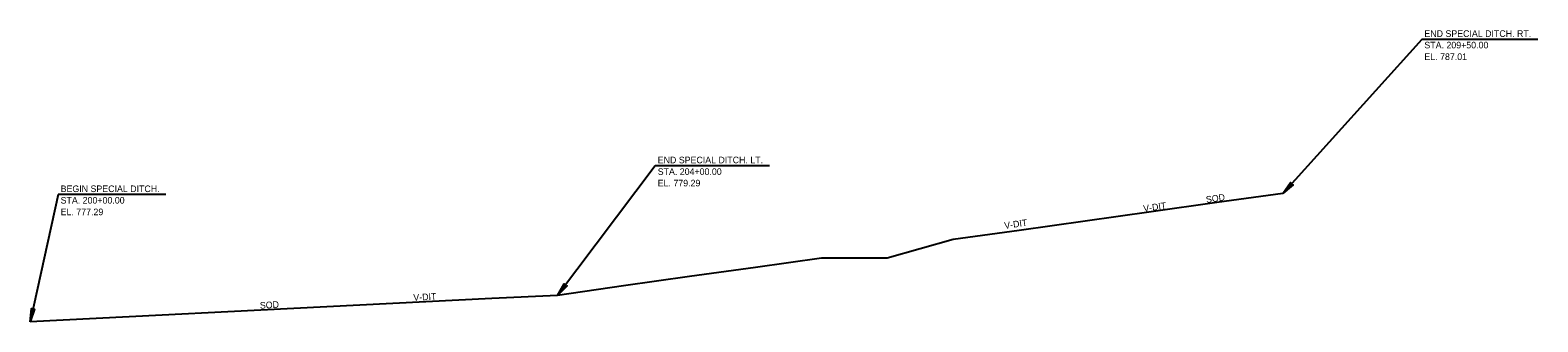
# Model space of a CAD drawing. Extents: x -50 to 1838305, y -27 to 820775.
# Drawn here: x 1837162 to 1838305, y 820554 to 820775 of the extents above; entities that cross this region are included whole.
import ezdxf

# ---------------------------------------------------------------- set-up
doc = ezdxf.new("R2010")
doc.units = 0
doc.layers.add('DESIGN - DRAINAGE - Special Ditches', color=7, linetype='Continuous')
doc.layers.add('DESIGN - PROFILE - Drainage - Bridges Drains and Ditches Text', color=7, linetype='Continuous')

msp = doc.modelspace()

# ---------------------------------------------------------------- linework, layer by layer
at = {"layer": 'DESIGN - DRAINAGE - Special Ditches'}
msp.add_lwpolyline([(1838111.6, 820651.5), (1838061.6, 820644.5), (1838011.6, 820637.5), (1837961.6, 820630.5), (1837911.6, 820623.5), (1837861.6, 820616.5), (1837811.6, 820602.5), (1837761.6, 820602.5), (1837711.6, 820595.5), (1837661.6, 820588.5), (1837611.6, 820581.5), (1837561.6, 820574.3), (1837511.6, 820571.8), (1837461.6, 820569.3), (1837411.6, 820566.8), (1837361.6, 820564.3), (1837311.6, 820561.8), (1837261.6, 820559.3), (1837211.6, 820556.8), (1837161.6, 820554.3)], dxfattribs=at)
at = {"layer": 'DESIGN - PROFILE - Drainage - Bridges Drains and Ditches Text'}
for p, q in [((1838304.9, 820768.1), (1838216.9, 820768.1)), ((1837722.3, 820672.4), (1837635.5, 820672.4)), ((1837264.5, 820650.6), (1837182.7, 820650.6))]:
    msp.add_line(p, q, dxfattribs=at)
for points in [[(1838216.9, 820768.1), (1838111.6, 820651.5)], [(1837635.5, 820672.4), (1837561.6, 820574.3)], [(1838111.6, 820651.5), (1838117.4, 820659.8), (1838117.4, 820658), (1838119.3, 820658.1), (1838111.6, 820651.5)], [(1837182.7, 820650.6), (1837161.6, 820554.3)], [(1837561.6, 820574.3), (1837566.6, 820583.1), (1837566.8, 820581.3), (1837568.7, 820581.5), (1837561.6, 820574.3)], [(1837161.6, 820554.3), (1837162.5, 820564.4), (1837163.5, 820562.8), (1837165, 820563.8), (1837161.6, 820554.3)]]:
    msp.add_lwpolyline(points, dxfattribs=at)
for points in [[(1838111.6, 820651.5), (1838117.4, 820659.8), (1838117.4, 820658), (1838119.3, 820658.1)], [(1837561.6, 820574.3), (1837566.6, 820583.1), (1837566.8, 820581.3), (1837568.7, 820581.5)], [(1837161.6, 820554.3), (1837162.5, 820564.4), (1837163.5, 820562.8), (1837165, 820563.8)]]:
    msp.add_lwpolyline(points, close=True, dxfattribs=at)

# ---------------------------------------------------------------- texts
at = {"layer": 'DESIGN - DRAINAGE - Special Ditches'}
for s, rotation, p in [('SOD', 7.9696, (1838053.6, 820644.3)), ('V-DIT', 7.9696, (1838006.1, 820637.5)), ('V-DIT', 7.9696, (1837900.7, 820624.6)), ('SOD', 2.8624, (1837335.9, 820564.2)), ('V-DIT', 2.8624, (1837452.3, 820570.2))]:
    msp.add_text(s, height=5, rotation=rotation, dxfattribs=at).set_placement(p)
at = {"layer": 'DESIGN - PROFILE - Drainage - Bridges Drains and Ditches Text'}
for s, p in [('END SPECIAL DITCH. RT.', (1838218.9, 820770)), ('STA. 209+50.00', (1838218.9, 820761.3)), ('EL. 787.01', (1838218.9, 820752.5)), ('STA. 204+00.00', (1837637.5, 820665.5)), ('END SPECIAL DITCH. LT.', (1837637.5, 820674.3)), ('EL. 779.29', (1837637.5, 820656.8)), ('STA. 200+00.00', (1837184.7, 820643.8)), ('BEGIN SPECIAL DITCH.', (1837184.7, 820652.5)), ('EL. 777.29', (1837184.7, 820635))]:
    msp.add_text(s, height=5, dxfattribs=at).set_placement(p)

doc.saveas('drawing.dxf')
